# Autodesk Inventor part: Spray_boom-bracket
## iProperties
Created: 2007-04
Part Number: Spray_boom-bracket
Material: Steel
Document SubType Name: Modeling
Designer: Admin
Mass: 12361.5 g
Surface Area: 1292.59 cm^2
Volume: 1574.71 cm^3
Density: 7.85 g/cm^3
Author: Admin
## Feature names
1. Extrusion1
2. Extrusion2
3. Extrusion3
4. Chamfer1
